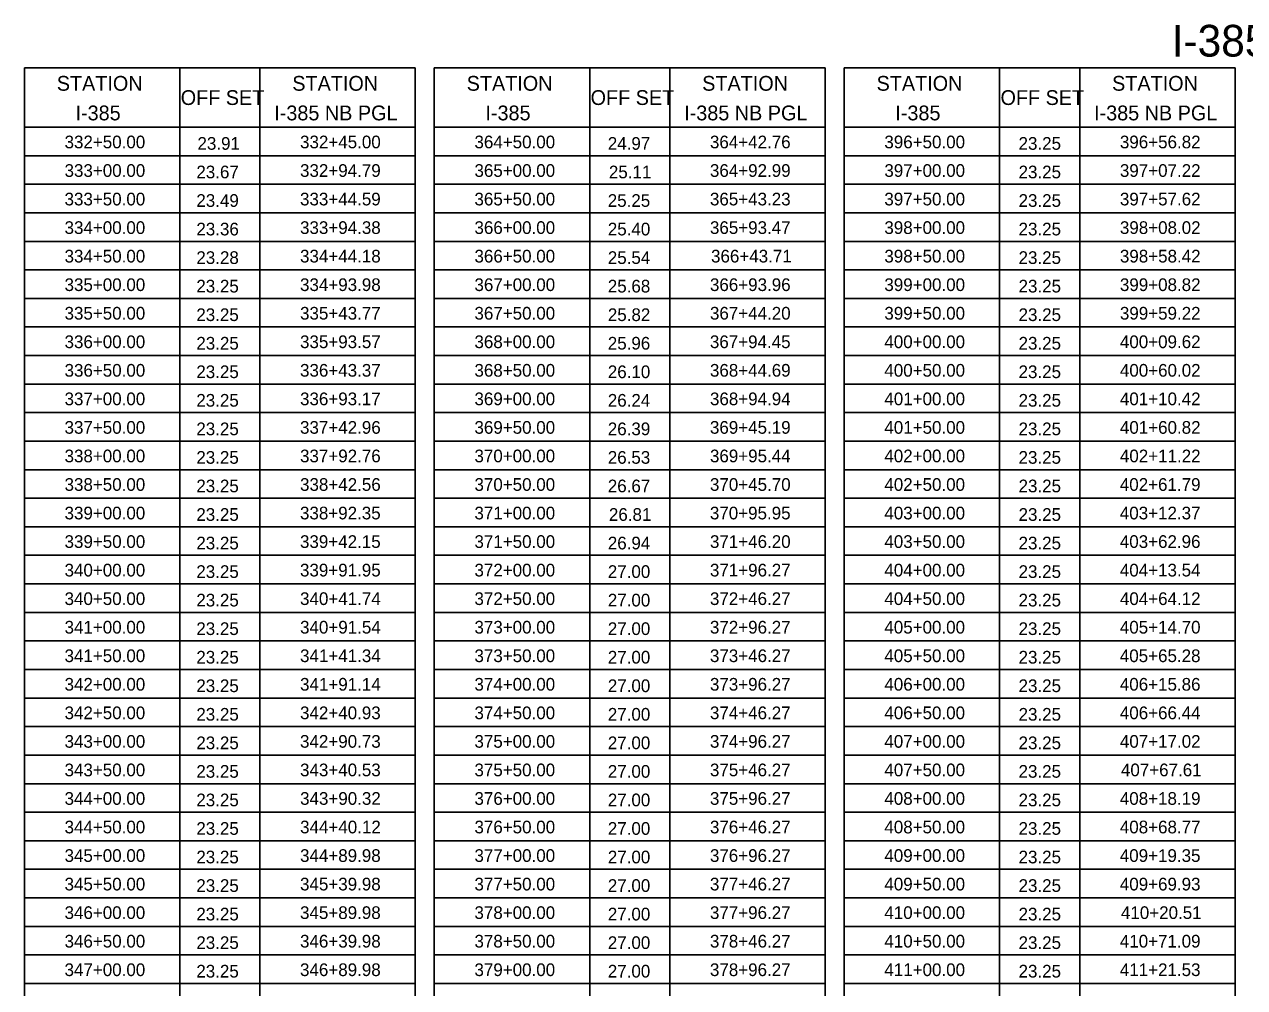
# Model space of a CAD drawing. Extents: x 1602163 to 1612907, y 1087635 to 1096265.
# Drawn here: x 1609604 to 1610181, y 1095755 to 1096210 of the extents above; entities that cross this region are included whole.
import ezdxf

# ---------------------------------------------------------------- set-up
doc = ezdxf.new("R2010")
doc.units = 0
doc.layers.add('RD_SHT_Misc1', color=7, linetype='Continuous')
doc.layers.add('RD_SHT_TX', color=7, linetype='Continuous')

msp = doc.modelspace()

# ---------------------------------------------------------------- linework, layer by layer
at = {"layer": 'RD_SHT_Misc1'}
for p, q in [((1609604.34, 1096189.84), (1609604.34, 1095297.84)), ((1609604.34, 1096189.84), (1609789.17, 1096189.84)), ((1609677.81, 1096189.84), (1609677.81, 1095297.84)), ((1609715.7, 1096189.84), (1609715.7, 1095297.84)), ((1609789.17, 1096189.84), (1609789.17, 1095297.84)), ((1609798.17, 1096189.84), (1609798.17, 1095297.84)), ((1609798.17, 1096189.84), (1609983, 1096189.84)), ((1609871.64, 1096189.84), (1609871.64, 1095297.84)), ((1609909.53, 1096189.84), (1609909.53, 1095297.84)), ((1609983, 1096189.84), (1609983, 1095297.84)), ((1609992, 1096189.84), (1609992, 1095297.84)), ((1609992, 1096189.84), (1610176.83, 1096189.84)), ((1610065.47, 1096189.84), (1610065.47, 1095297.84)), ((1610103.36, 1096189.84), (1610103.36, 1095297.84)), ((1610176.83, 1096189.84), (1610176.83, 1095297.84)), ((1609604.34, 1096161.84), (1609789.17, 1096161.84)), ((1609798.17, 1096161.84), (1609983, 1096161.84)), ((1609992, 1096161.84), (1610176.83, 1096161.84)), ((1609604.34, 1096148.34), (1609789.17, 1096148.34)), ((1609798.17, 1096148.34), (1609983, 1096148.34)), ((1609992, 1096148.34), (1610176.83, 1096148.34)), ((1609604.34, 1096134.84), (1609789.17, 1096134.84)), ((1609798.17, 1096134.84), (1609983, 1096134.84)), ((1609992, 1096134.84), (1610176.83, 1096134.84)), ((1609604.34, 1096121.34), (1609789.17, 1096121.34)), ((1609798.17, 1096121.34), (1609983, 1096121.34)), ((1609992, 1096121.34), (1610176.83, 1096121.34)), ((1609604.34, 1096107.84), (1609789.17, 1096107.84)), ((1609798.17, 1096107.84), (1609983, 1096107.84)), ((1609992, 1096107.84), (1610176.83, 1096107.84)), ((1609604.34, 1096094.34), (1609789.17, 1096094.34)), ((1609798.17, 1096094.34), (1609983, 1096094.34)), ((1609992, 1096094.34), (1610176.83, 1096094.34)), ((1609604.34, 1096080.84), (1609789.17, 1096080.84)), ((1609798.17, 1096080.84), (1609983, 1096080.84)), ((1609992, 1096080.84), (1610176.83, 1096080.84)), ((1609604.34, 1096067.34), (1609789.17, 1096067.34)), ((1609798.17, 1096067.34), (1609983, 1096067.34)), ((1609992, 1096067.34), (1610176.83, 1096067.34)), ((1609604.34, 1096053.84), (1609789.17, 1096053.84)), ((1609798.17, 1096053.84), (1609983, 1096053.84)), ((1609992, 1096053.84), (1610176.83, 1096053.84)), ((1609604.34, 1096040.34), (1609789.17, 1096040.34)), ((1609798.17, 1096040.34), (1609983, 1096040.34)), ((1609992, 1096040.34), (1610176.83, 1096040.34)), ((1609604.34, 1096026.84), (1609789.17, 1096026.84)), ((1609798.17, 1096026.84), (1609983, 1096026.84)), ((1609992, 1096026.84), (1610176.83, 1096026.84)), ((1609604.34, 1096013.34), (1609789.17, 1096013.34)), ((1609798.17, 1096013.34), (1609983, 1096013.34)), ((1609992, 1096013.34), (1610176.83, 1096013.34)), ((1609604.34, 1095999.84), (1609789.17, 1095999.84)), ((1609798.17, 1095999.84), (1609983, 1095999.84)), ((1609992, 1095999.84), (1610176.83, 1095999.84)), ((1609604.34, 1095986.34), (1609789.17, 1095986.34)), ((1609798.17, 1095986.34), (1609983, 1095986.34)), ((1609992, 1095986.34), (1610176.83, 1095986.34)), ((1609604.34, 1095972.84), (1609789.17, 1095972.84)), ((1609798.17, 1095972.84), (1609983, 1095972.84)), ((1609992, 1095972.84), (1610176.83, 1095972.84)), ((1609604.34, 1095959.34), (1609789.17, 1095959.34)), ((1609798.17, 1095959.34), (1609983, 1095959.34)), ((1609992, 1095959.34), (1610176.83, 1095959.34)), ((1609604.34, 1095945.84), (1609789.17, 1095945.84)), ((1609798.17, 1095945.84), (1609983, 1095945.84)), ((1609992, 1095945.84), (1610176.83, 1095945.84)), ((1609604.34, 1095932.34), (1609789.17, 1095932.34)), ((1609798.17, 1095932.34), (1609983, 1095932.34)), ((1609992, 1095932.34), (1610176.83, 1095932.34)), ((1609604.34, 1095918.84), (1609789.17, 1095918.84)), ((1609798.17, 1095918.84), (1609983, 1095918.84)), ((1609992, 1095918.84), (1610176.83, 1095918.84)), ((1609604.34, 1095905.34), (1609789.17, 1095905.34)), ((1609798.17, 1095905.34), (1609983, 1095905.34)), ((1609992, 1095905.34), (1610176.83, 1095905.34)), ((1609604.34, 1095891.84), (1609789.17, 1095891.84)), ((1609798.17, 1095891.84), (1609983, 1095891.84)), ((1609992, 1095891.84), (1610176.83, 1095891.84)), ((1609604.34, 1095878.34), (1609789.17, 1095878.34)), ((1609798.17, 1095878.34), (1609983, 1095878.34)), ((1609992, 1095878.34), (1610176.83, 1095878.34)), ((1609604.34, 1095864.84), (1609789.17, 1095864.84)), ((1609798.17, 1095864.84), (1609983, 1095864.84)), ((1609992, 1095864.84), (1610176.83, 1095864.84)), ((1609604.34, 1095851.34), (1609789.17, 1095851.34)), ((1609798.17, 1095851.34), (1609983, 1095851.34)), ((1609992, 1095851.34), (1610176.83, 1095851.34)), ((1609604.34, 1095837.84), (1609789.17, 1095837.84)), ((1609798.17, 1095837.84), (1609983, 1095837.84)), ((1609992, 1095837.84), (1610176.83, 1095837.84)), ((1609604.34, 1095824.34), (1609789.17, 1095824.34)), ((1609798.17, 1095824.34), (1609983, 1095824.34)), ((1609992, 1095824.34), (1610176.83, 1095824.34)), ((1609604.34, 1095810.84), (1609789.17, 1095810.84)), ((1609798.17, 1095810.84), (1609983, 1095810.84)), ((1609992, 1095810.84), (1610176.83, 1095810.84)), ((1609604.34, 1095797.34), (1609789.17, 1095797.34)), ((1609798.17, 1095797.34), (1609983, 1095797.34)), ((1609992, 1095797.34), (1610176.83, 1095797.34)), ((1609604.34, 1095783.84), (1609789.17, 1095783.84)), ((1609798.17, 1095783.84), (1609983, 1095783.84)), ((1609992, 1095783.84), (1610176.83, 1095783.84)), ((1609604.34, 1095770.34), (1609789.17, 1095770.34)), ((1609798.17, 1095770.34), (1609983, 1095770.34)), ((1609992, 1095770.34), (1610176.83, 1095770.34)), ((1609604.34, 1095756.84), (1609789.17, 1095756.84)), ((1609798.17, 1095756.84), (1609983, 1095756.84)), ((1609992, 1095756.84), (1610176.83, 1095756.84))]:
    msp.add_line(p, q, dxfattribs=at)

# ---------------------------------------------------------------- texts
at = {"layer": 'RD_SHT_TX'}
for s, height, p in [('I-385 TO PGL STATION AND OFF SET TABLES', 15, (1610146.87, 1096195.23)), ('STATION', 7, (1609619.66, 1096179.07)), ('STATION', 7, (1609731.02, 1096179.07)), ('STATION', 7, (1609813.49, 1096179.07)), ('STATION', 7, (1609924.85, 1096179.07)), ('STATION', 7, (1610007.32, 1096179.07)), ('STATION', 7, (1610118.68, 1096179.07)), ('OFF SET', 7, (1609678.26, 1096172.34)), ('OFF SET', 7, (1609872.09, 1096172.34)), ('OFF SET', 7, (1610065.92, 1096172.34)), ('I-385', 7, (1609628.52, 1096165.07)), ('I-385 NB PGL', 7, (1609722.5, 1096165.07)), ('I-385', 7, (1609822.35, 1096165.07)), ('I-385 NB PGL', 7, (1609916.33, 1096165.07)), ('I-385', 7, (1610016.18, 1096165.07)), ('I-385 NB PGL', 7, (1610110.16, 1096165.07)), ('332+50.00', 6, (1609623.33, 1096151.84)), ('23.91', 6, (1609686.18, 1096151.15)), ('332+45.00', 6, (1609734.69, 1096151.84)), ('364+50.00', 6, (1609817.16, 1096151.84)), ('24.97', 6, (1609880.21, 1096151.15)), ('364+42.76', 6, (1609928.51, 1096151.84)), ('396+50.00', 6, (1610010.99, 1096151.84)), ('23.25', 6, (1610074.45, 1096151.15)), ('396+56.82', 6, (1610122.37, 1096151.84)), ('333+00.00', 6, (1609623.33, 1096138.34)), ('332+94.79', 6, (1609734.68, 1096138.34)), ('365+00.00', 6, (1609817.16, 1096138.34)), ('364+92.99', 6, (1609928.51, 1096138.34)), ('397+00.00', 6, (1610010.99, 1096138.34)), ('397+07.22', 6, (1610122.37, 1096138.34)), ('23.67', 6, (1609685.66, 1096137.65)), ('25.11', 6, (1609880.73, 1096137.65)), ('23.25', 6, (1610074.45, 1096137.65)), ('333+50.00', 6, (1609623.33, 1096124.84)), ('23.49', 6, (1609685.65, 1096124.15)), ('333+44.59', 6, (1609734.68, 1096124.84)), ('365+50.00', 6, (1609817.16, 1096124.84)), ('25.25', 6, (1609880.19, 1096124.15)), ('365+43.23', 6, (1609928.51, 1096124.84)), ('397+50.00', 6, (1610010.99, 1096124.84)), ('23.25', 6, (1610074.45, 1096124.15)), ('397+57.62', 6, (1610122.37, 1096124.84)), ('334+00.00', 6, (1609623.33, 1096111.34)), ('23.36', 6, (1609685.66, 1096110.65)), ('333+94.38', 6, (1609734.68, 1096111.34)), ('366+00.00', 6, (1609817.16, 1096111.34)), ('25.40', 6, (1609880.22, 1096110.65)), ('365+93.47', 6, (1609928.51, 1096111.34)), ('398+00.00', 6, (1610010.99, 1096111.34)), ('23.25', 6, (1610074.45, 1096110.65)), ('398+08.02', 6, (1610122.37, 1096111.34)), ('334+50.00', 6, (1609623.33, 1096097.84)), ('334+44.18', 6, (1609734.68, 1096097.84)), ('366+50.00', 6, (1609817.16, 1096097.84)), ('366+43.71', 6, (1609929.03, 1096097.84)), ('398+50.00', 6, (1610010.99, 1096097.84)), ('398+58.42', 6, (1610122.37, 1096097.84)), ('23.28', 6, (1609685.65, 1096097.15)), ('25.54', 6, (1609880.22, 1096097.15)), ('23.25', 6, (1610074.45, 1096097.15)), ('335+00.00', 6, (1609623.33, 1096084.34)), ('23.25', 6, (1609685.64, 1096083.65)), ('334+93.98', 6, (1609734.68, 1096084.34)), ('367+00.00', 6, (1609817.16, 1096084.34)), ('25.68', 6, (1609880.21, 1096083.65)), ('366+93.96', 6, (1609928.51, 1096084.34)), ('399+00.00', 6, (1610010.99, 1096084.34)), ('23.25', 6, (1610074.45, 1096083.65)), ('399+08.82', 6, (1610122.37, 1096084.34)), ('335+50.00', 6, (1609623.33, 1096070.84)), ('23.25', 6, (1609685.64, 1096070.15)), ('335+43.77', 6, (1609734.68, 1096070.84)), ('367+50.00', 6, (1609817.16, 1096070.84)), ('25.82', 6, (1609880.24, 1096070.15)), ('367+44.20', 6, (1609928.52, 1096070.84)), ('399+50.00', 6, (1610010.99, 1096070.84)), ('23.25', 6, (1610074.45, 1096070.15)), ('399+59.22', 6, (1610122.37, 1096070.84)), ('336+00.00', 6, (1609623.33, 1096057.34)), ('335+93.57', 6, (1609734.68, 1096057.34)), ('368+00.00', 6, (1609817.16, 1096057.34)), ('367+94.45', 6, (1609928.49, 1096057.34)), ('400+00.00', 6, (1610010.99, 1096057.34)), ('400+09.62', 6, (1610122.37, 1096057.34)), ('23.25', 6, (1609685.64, 1096056.65)), ('25.96', 6, (1609880.21, 1096056.65)), ('23.25', 6, (1610074.45, 1096056.65)), ('336+50.00', 6, (1609623.33, 1096043.84)), ('23.25', 6, (1609685.64, 1096043.15)), ('336+43.37', 6, (1609734.68, 1096043.84)), ('368+50.00', 6, (1609817.16, 1096043.84)), ('26.10', 6, (1609880.22, 1096043.15)), ('368+44.69', 6, (1609928.51, 1096043.84)), ('400+50.00', 6, (1610010.99, 1096043.84)), ('23.25', 6, (1610074.45, 1096043.15)), ('400+60.02', 6, (1610122.37, 1096043.84)), ('337+00.00', 6, (1609623.33, 1096030.34)), ('23.25', 6, (1609685.64, 1096029.65)), ('336+93.17', 6, (1609734.68, 1096030.34)), ('369+00.00', 6, (1609817.16, 1096030.34)), ('26.24', 6, (1609880.22, 1096029.65)), ('368+94.94', 6, (1609928.52, 1096030.34)), ('401+00.00', 6, (1610010.99, 1096030.34)), ('23.25', 6, (1610074.45, 1096029.65)), ('401+10.42', 6, (1610122.37, 1096030.34)), ('337+50.00', 6, (1609623.33, 1096016.84)), ('337+42.96', 6, (1609734.68, 1096016.84)), ('369+50.00', 6, (1609817.16, 1096016.84)), ('369+45.19', 6, (1609928.51, 1096016.84)), ('401+50.00', 6, (1610010.99, 1096016.84)), ('401+60.82', 6, (1610122.37, 1096016.84)), ('23.25', 6, (1609685.64, 1096016.15)), ('26.39', 6, (1609880.21, 1096016.15)), ('23.25', 6, (1610074.45, 1096016.15)), ('338+00.00', 6, (1609623.33, 1096003.34)), ('23.25', 6, (1609685.64, 1096002.65)), ('337+92.76', 6, (1609734.68, 1096003.34)), ('370+00.00', 6, (1609817.16, 1096003.34)), ('26.53', 6, (1609880.21, 1096002.65)), ('369+95.44', 6, (1609928.52, 1096003.34)), ('402+00.00', 6, (1610010.99, 1096003.34)), ('23.25', 6, (1610074.45, 1096002.65)), ('402+11.22', 6, (1610122.37, 1096003.34)), ('338+50.00', 6, (1609623.33, 1095989.84)), ('23.25', 6, (1609685.64, 1095989.15)), ('338+42.56', 6, (1609734.68, 1095989.84)), ('370+50.00', 6, (1609817.16, 1095989.84)), ('26.67', 6, (1609880.21, 1095989.15)), ('370+45.70', 6, (1609928.52, 1095989.84)), ('402+50.00', 6, (1610010.99, 1095989.84)), ('23.25', 6, (1610074.45, 1095989.15)), ('402+61.79', 6, (1610122.34, 1095989.84)), ('339+00.00', 6, (1609623.33, 1095976.34)), ('338+92.35', 6, (1609734.66, 1095976.34)), ('371+00.00', 6, (1609817.16, 1095976.34)), ('370+95.95', 6, (1609928.49, 1095976.34)), ('403+00.00', 6, (1610010.99, 1095976.34)), ('403+12.37', 6, (1610122.34, 1095976.34)), ('23.25', 6, (1609685.64, 1095975.65)), ('26.81', 6, (1609880.73, 1095975.65)), ('23.25', 6, (1610074.45, 1095975.65)), ('339+50.00', 6, (1609623.33, 1095962.84)), ('23.25', 6, (1609685.64, 1095962.15)), ('339+42.15', 6, (1609734.66, 1095962.84)), ('371+50.00', 6, (1609817.16, 1095962.84)), ('26.94', 6, (1609880.22, 1095962.15)), ('371+46.20', 6, (1609928.52, 1095962.84)), ('403+50.00', 6, (1610010.99, 1095962.84)), ('23.25', 6, (1610074.45, 1095962.15)), ('403+62.96', 6, (1610122.34, 1095962.84)), ('340+00.00', 6, (1609623.33, 1095949.34)), ('23.25', 6, (1609685.64, 1095948.65)), ('339+91.95', 6, (1609734.66, 1095949.34)), ('372+00.00', 6, (1609817.16, 1095949.34)), ('27.00', 6, (1609880.22, 1095948.65)), ('371+96.27', 6, (1609928.51, 1095949.34)), ('404+00.00', 6, (1610010.99, 1095949.34)), ('23.25', 6, (1610074.45, 1095948.65)), ('404+13.54', 6, (1610122.35, 1095949.34)), ('340+50.00', 6, (1609623.33, 1095935.84)), ('340+41.74', 6, (1609734.69, 1095935.84)), ('372+50.00', 6, (1609817.16, 1095935.84)), ('372+46.27', 6, (1609928.51, 1095935.84)), ('404+50.00', 6, (1610010.99, 1095935.84)), ('404+64.12', 6, (1610122.37, 1095935.84)), ('23.25', 6, (1609685.64, 1095935.15)), ('27.00', 6, (1609880.22, 1095935.15)), ('23.25', 6, (1610074.45, 1095935.15)), ('341+00.00', 6, (1609623.33, 1095922.34)), ('23.25', 6, (1609685.64, 1095921.65)), ('340+91.54', 6, (1609734.69, 1095922.34)), ('373+00.00', 6, (1609817.16, 1095922.34)), ('27.00', 6, (1609880.22, 1095921.65)), ('372+96.27', 6, (1609928.51, 1095922.34)), ('405+00.00', 6, (1610010.99, 1095922.34)), ('23.25', 6, (1610074.45, 1095921.65)), ('405+14.70', 6, (1610122.35, 1095922.34)), ('341+50.00', 6, (1609623.33, 1095908.84)), ('23.25', 6, (1609685.64, 1095908.15)), ('341+41.34', 6, (1609734.69, 1095908.84)), ('373+50.00', 6, (1609817.16, 1095908.84)), ('27.00', 6, (1609880.22, 1095908.15)), ('373+46.27', 6, (1609928.51, 1095908.84)), ('405+50.00', 6, (1610010.99, 1095908.84)), ('23.25', 6, (1610074.45, 1095908.15)), ('405+65.28', 6, (1610122.34, 1095908.84)), ('342+00.00', 6, (1609623.33, 1095895.34)), ('23.25', 6, (1609685.64, 1095894.65)), ('341+91.14', 6, (1609734.69, 1095895.34)), ('374+00.00', 6, (1609817.16, 1095895.34)), ('27.00', 6, (1609880.22, 1095894.65)), ('373+96.27', 6, (1609928.51, 1095895.34)), ('406+00.00', 6, (1610010.99, 1095895.34)), ('23.25', 6, (1610074.45, 1095894.65)), ('406+15.86', 6, (1610122.34, 1095895.34)), ('342+50.00', 6, (1609623.33, 1095881.84)), ('23.25', 6, (1609685.64, 1095881.15)), ('342+40.93', 6, (1609734.68, 1095881.84)), ('374+50.00', 6, (1609817.16, 1095881.84)), ('27.00', 6, (1609880.22, 1095881.15)), ('374+46.27', 6, (1609928.51, 1095881.84)), ('406+50.00', 6, (1610010.99, 1095881.84)), ('23.25', 6, (1610074.45, 1095881.15)), ('406+66.44', 6, (1610122.35, 1095881.84)), ('343+00.00', 6, (1609623.33, 1095868.34)), ('23.25', 6, (1609685.64, 1095867.65)), ('342+90.73', 6, (1609734.68, 1095868.34)), ('375+00.00', 6, (1609817.16, 1095868.34)), ('27.00', 6, (1609880.22, 1095867.65)), ('374+96.27', 6, (1609928.51, 1095868.34)), ('407+00.00', 6, (1610010.99, 1095868.34)), ('23.25', 6, (1610074.45, 1095867.65)), ('407+17.02', 6, (1610122.37, 1095868.34)), ('343+50.00', 6, (1609623.33, 1095854.84)), ('23.25', 6, (1609685.64, 1095854.15)), ('343+40.53', 6, (1609734.68, 1095854.84)), ('375+50.00', 6, (1609817.16, 1095854.84)), ('27.00', 6, (1609880.22, 1095854.15)), ('375+46.27', 6, (1609928.51, 1095854.84)), ('407+50.00', 6, (1610010.99, 1095854.84)), ('23.25', 6, (1610074.45, 1095854.15)), ('407+67.61', 6, (1610122.86, 1095854.84)), ('344+00.00', 6, (1609623.33, 1095841.34)), ('23.25', 6, (1609685.64, 1095840.65)), ('343+90.32', 6, (1609734.71, 1095841.34)), ('376+00.00', 6, (1609817.16, 1095841.34)), ('27.00', 6, (1609880.22, 1095840.65)), ('375+96.27', 6, (1609928.51, 1095841.34)), ('408+00.00', 6, (1610010.99, 1095841.34)), ('23.25', 6, (1610074.45, 1095840.65)), ('408+18.19', 6, (1610122.34, 1095841.34)), ('344+50.00', 6, (1609623.33, 1095827.84)), ('23.25', 6, (1609685.64, 1095827.15)), ('344+40.12', 6, (1609734.71, 1095827.84)), ('376+50.00', 6, (1609817.16, 1095827.84)), ('27.00', 6, (1609880.22, 1095827.15)), ('376+46.27', 6, (1609928.51, 1095827.84)), ('408+50.00', 6, (1610010.99, 1095827.84)), ('23.25', 6, (1610074.45, 1095827.15)), ('408+68.77', 6, (1610122.34, 1095827.84)), ('345+00.00', 6, (1609623.33, 1095814.34)), ('23.25', 6, (1609685.64, 1095813.65)), ('344+89.98', 6, (1609734.68, 1095814.34)), ('377+00.00', 6, (1609817.16, 1095814.34)), ('27.00', 6, (1609880.22, 1095813.65)), ('376+96.27', 6, (1609928.51, 1095814.34)), ('409+00.00', 6, (1610010.99, 1095814.34)), ('23.25', 6, (1610074.45, 1095813.65)), ('409+19.35', 6, (1610122.32, 1095814.34)), ('345+50.00', 6, (1609623.33, 1095800.84)), ('23.25', 6, (1609685.64, 1095800.15)), ('345+39.98', 6, (1609734.68, 1095800.84)), ('377+50.00', 6, (1609817.16, 1095800.84)), ('27.00', 6, (1609880.22, 1095800.15)), ('377+46.27', 6, (1609928.51, 1095800.84)), ('409+50.00', 6, (1610010.99, 1095800.84)), ('23.25', 6, (1610074.45, 1095800.15)), ('409+69.93', 6, (1610122.34, 1095800.84)), ('346+00.00', 6, (1609623.33, 1095787.34)), ('23.25', 6, (1609685.64, 1095786.65)), ('345+89.98', 6, (1609734.68, 1095787.34)), ('378+00.00', 6, (1609817.16, 1095787.34)), ('27.00', 6, (1609880.22, 1095786.65)), ('377+96.27', 6, (1609928.51, 1095787.34)), ('410+00.00', 6, (1610010.99, 1095787.34)), ('23.25', 6, (1610074.45, 1095786.65)), ('410+20.51', 6, (1610122.86, 1095787.34)), ('346+50.00', 6, (1609623.33, 1095773.84)), ('23.25', 6, (1609685.64, 1095773.15)), ('346+39.98', 6, (1609734.68, 1095773.84)), ('378+50.00', 6, (1609817.16, 1095773.84)), ('27.00', 6, (1609880.22, 1095773.15)), ('378+46.27', 6, (1609928.51, 1095773.84)), ('410+50.00', 6, (1610010.99, 1095773.84)), ('23.25', 6, (1610074.45, 1095773.15)), ('410+71.09', 6, (1610122.34, 1095773.84)), ('347+00.00', 6, (1609623.33, 1095760.34)), ('23.25', 6, (1609685.64, 1095759.65)), ('346+89.98', 6, (1609734.68, 1095760.34)), ('379+00.00', 6, (1609817.16, 1095760.34)), ('27.00', 6, (1609880.22, 1095759.65)), ('378+96.27', 6, (1609928.51, 1095760.34)), ('411+00.00', 6, (1610010.99, 1095760.34)), ('23.25', 6, (1610074.45, 1095759.65)), ('411+21.53', 6, (1610122.34, 1095760.34))]:
    msp.add_text(s, height=height, dxfattribs=at).set_placement(p)

doc.saveas('drawing.dxf')
